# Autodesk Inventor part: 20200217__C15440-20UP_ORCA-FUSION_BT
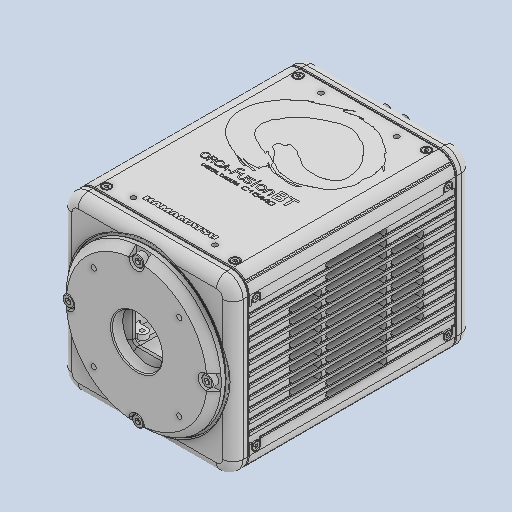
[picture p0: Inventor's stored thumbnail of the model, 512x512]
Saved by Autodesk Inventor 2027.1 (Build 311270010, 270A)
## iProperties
Created: 2020-02
Part Number: 20200217__C15440-20UP_ORCA-FUSION_BT
Material: Generic
Description: STEP AP203
Document SubType Name: Modeling
Designer: dunge
Density: 1 g/cm^3
Appearance: Default
Title: 20200217__C15440-20UP_ORCA-FUSION_BT.STEP
Revision Number: ANY
Sending System: SolidWorks 2018
Preprocessor: SwSTEP 2.0
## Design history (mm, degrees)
feature "B1084-01__B1064-10E01A__FRONT-PANEL-2-solid1"
feature "B1084-01G02__HS-BASE-4_B1084-01__B1064-10__kqb2l06_m5-1-soli"
feature "B1084-01G02__HS-BASE-4_B1084-01__B1064-10__kqb2l06_m5-2-soli"
feature "B1084-01_B1064-10C02__REAR-PANEL_SILK-1_B1064-10C02__REAR-PA"
feature "B1084-01_B1064-10C02__REAR-PANEL_SILK-1_B1064-10C02__REAR-PA"
feature "B1084-01_B1064-10C02__REAR-PANEL_SILK-1_B1064-10C02__REAR-PA"
feature "B1084-01_B1064-10C02__REAR-PANEL_SILK-1_B1064-10C02__REAR-PA"
feature "B1084-01_B1064-10C02__REAR-PANEL_SILK-1_B1064-10C02__REAR-PA"
feature "B1084-01_B1064-10C02__REAR-PANEL_SILK-1_B1064-10C02__REAR-PA"
feature "B1084-01_B1064-10C02__REAR-PANEL_SILK-1_B1064-10C02__REAR-PA"
feature "B1084-01_B1064-10C02__REAR-PANEL_SILK-1_B1064-10C02__REAR-PA"
feature "B1084-01_B1064-10C02__REAR-PANEL_SILK-1_B1064-10C02__REAR-PA"
feature "B1084-01_B1064-10C02__REAR-PANEL_SILK-1_B1064-10C02__REAR-PA"
feature "B1084-01_B1064-10C02__REAR-PANEL_SILK-1_B1064-10C02__REAR-PA"
feature "B1084-01_B1064-10C02__REAR-PANEL_SILK-1_B1064-10C02__REAR-PA"
feature "B1084-01_B1064-10C02__REAR-PANEL_SILK-1_B1064-10C02__REAR-PA"
feature "B1084-01_B1064-10C02__REAR-PANEL_SILK-1_B1064-10C02__REAR-PA"
feature "B1084-01_B1064-10C02__REAR-PANEL_SILK-1_B1064-10C02__REAR-PA"
feature "B1084-01_B1064-10C02__REAR-PANEL_SILK-1_B1064-10C02__REAR-PA"
feature "B1084-01_B1064-10C02__REAR-PANEL_SILK-1_B1064-10C02__REAR-PA"
feature "B1084-01_B1064-10C02__REAR-PANEL_SILK-1_B1064-10C02__REAR-PA"
feature "B1084-01_B1064-10C02__REAR-PANEL_SILK-1_B1064-10C02__REAR-PA"
feature "B1084-01_B1064-10C02__REAR-PANEL_SILK-1_B1064-10C02__REAR-PA"
feature "B1084-01_B1064-10C02__REAR-PANEL_SILK-1_B1064-10C02__REAR-PA"
feature "B1084-01_B1064-10C02__REAR-PANEL_SILK-1_B1064-10C02__REAR-PA"
feature "B1084-01_B1064-10C02__REAR-PANEL_SILK-1_B1064-10C02__REAR-PA"
feature "B1084-01_B1064-10C02__REAR-PANEL_SILK-1_B1064-10C02__REAR-PA"
feature "B1084-01_B1064-10C02__REAR-PANEL_SILK-1_B1064-10C02__REAR-PA"
feature "B1084-01_B1064-10C02__REAR-PANEL_SILK-1_B1064-10C02__REAR-PA"
feature "B1084-01_B1064-10C02__REAR-PANEL_SILK-1_B1064-10C02__REAR-PA"
feature "B1084-01_B1064-10C02__REAR-PANEL_SILK-1_B1064-10C02__REAR-PA"
feature "B1084-01_B1064-10C02__REAR-PANEL_SILK-1_B1064-10C02__REAR-PA"
feature "B1084-01_B1064-10C02__REAR-PANEL_SILK-1_B1064-10C02__REAR-PA"
feature "B1084-01_B1064-10C02__REAR-PANEL_SILK-1_B1064-10C02__REAR-PA"
feature "B1084-01_B1064-10C02__REAR-PANEL_SILK-1_B1064-10C02__REAR-PA"
feature "B1084-01_B1064-10C02__REAR-PANEL_SILK-1_B1064-10C02__REAR-PA"
feature "B1084-01_B1064-10C02__REAR-PANEL_SILK-1_B1064-10C02__REAR-PA"
feature "B1084-01_B1064-10C02__REAR-PANEL_SILK-1_B1064-10C02__REAR-PA"
feature "B1084-01_B1064-10C02__REAR-PANEL_SILK-1_B1064-10C02__REAR-PA"
feature "B1084-01_B1064-10C02__REAR-PANEL_SILK-1_B1064-10C02__REAR-PA"
feature "B1084-01_B1064-10C02__REAR-PANEL_SILK-1_B1064-10C02__REAR-PA"
feature "B1084-01_B1064-10C02__REAR-PANEL_SILK-1_B1064-10C02__REAR-PA"
feature "B1084-01_B1064-10C02__REAR-PANEL_SILK-1_B1064-10C02__REAR-PA"
feature "B1084-01_B1064-10C02__REAR-PANEL_SILK-1_B1064-10C02__REAR-PA"
feature "B1084-01_B1064-10C02__REAR-PANEL_SILK-1_B1064-10C02__REAR-PA"
feature "B1084-01_B1064-10C02__REAR-PANEL_SILK-1_B1064-10C02__REAR-PA"
feature "B1084-01_B1064-10C02__REAR-PANEL_SILK-1_B1064-10C02__REAR-PA"
feature "B1084-01_B1064-10C02__REAR-PANEL_SILK-1_B1064-10C02__REAR-PA"
feature "B1084-01_B1064-10C02__REAR-PANEL_SILK-1_B1064-10C02__REAR-PA"
feature "B1084-01_B1064-10C02__REAR-PANEL_SILK-1_B1064-10C02__REAR-PA"
feature "B1084-01_B1064-10C02__REAR-PANEL_SILK-1_B1064-10C02__REAR-PA"
feature "B1084-01_B1064-10C02__REAR-PANEL_SILK-1_B1064-10C02__REAR-PA"
feature "B1084-01_B1064-10C02__REAR-PANEL_SILK-1_B1064-10C02__REAR-PA"
feature "B1084-01_B1064-10C02__REAR-PANEL_SILK-1_B1064-10C02__REAR-PA"
feature "B1084-01_B1064-10C02__REAR-PANEL_SILK-1_B1064-10C02__REAR-PA"
feature "B1084-01_B1064-10C02__REAR-PANEL_SILK-1_B1064-10C02__REAR-PA"
feature "B1084-01_B1064-10C02__REAR-PANEL_SILK-1_B1064-10C02__REAR-PA"
feature "B1084-01_B1064-10C02__REAR-PANEL_SILK-1_B1064-10C02__REAR-PA"
feature "B1084-01_B1064-10C02__REAR-PANEL_SILK-1_B1064-10C02__REAR-PA"
feature "B1084-01_B1064-10C02__REAR-PANEL_SILK-1_B1064-10C02__REAR-PA"
feature "B1084-01_B1064-10C02__REAR-PANEL_SILK-1_B1064-10C02__REAR-PA"
feature "B1084-01_B1064-10C02__REAR-PANEL_SILK-1_B1064-10C02__REAR-PA"
feature "B1084-01_B1064-10C02__REAR-PANEL_SILK-1_B1064-10C02__REAR-PA"
feature "B1084-01_B1064-10C02__REAR-PANEL_SILK-1_B1064-10C02__REAR-PA"
feature "B1084-01__B1064-10E03A__SIDE-COVER-R-1-solid1"
feature "B1084-01__B1064-10E04A__SIDE-COVER-L-1-solid1"
feature "B1084-01E05__TOP-COVER-1-solid1"
feature "B1084-01E05__TOP-COVER-1-solid2"
feature "B1084-01E06__BOTTOM-COVER-1-solid1"
feature "B1084-01__B1064-10A01__FB-SPACER-02-1-solid1"
feature "B1084-01__B1064-10A01__FB-SPACER-02-4-solid1"
feature "B1084-01__B1064-10A02__FB-SPACER-01-4-solid1"
feature "B1084-01__B1064-10B08__C-MOUNT-1-solid1"
feature "B1084-01__B1064-10A03__CONNE-COVER-1-solid1"
feature "B1084-01__¸§qlW__0Ôix2í__M2x4__3BC-1-solid1"
feature "B1084-01__¸§qlW__0Ôix2í__M2x4__3BC-2-solid1"
feature "B1084-01__Zpt«{g__M2x4__BK-1-solid1"
feature "B1084-01__Zpt«{g__M2x4__BK-2-solid1"
feature "B1084-01__Zpt«{g__M2x4__BK-3-solid1"
feature "B1084-01__Zpt«{g__M2x4__BK-4-solid1"
feature "B1084-01__Zpt«{g__M2x4__BK-5-solid1"
feature "B1084-01__Zpt«{g__M2x4__BK-6-solid1"
feature "B1084-01__Zpt«{g__M2x4__BK-7-solid1"
feature "B1084-01__Zpt«{g__M2x4__BK-8-solid1"
feature "B1084-01__Zpt«{g__M2x4__BK-9-solid1"
feature "B1084-01__Zpt«{g__M2x4__BK-10-solid1"
feature "B1084-01__Zpt«{g__M2x4__BK-11-solid1"
feature "B1084-01__Zpt«{g__M2x4__BK-12-solid1"
feature "B1084-01__Zpt«{g__M2x4__BK-13-solid1"
feature "B1084-01__Zpt«{g__M2x4__BK-14-solid1"
feature "B1084-01__Zpt«{g__M2x4__BK-15-solid1"
feature "B1084-01__Zpt«{g__M2x4__BK-16-solid1"
feature "B1084-01__Zpt«{g__M3x6__X-5-solid1"
feature "B1084-01__Zpt«{g__M3x6__X-6-solid1"
feature "B1084-01__Zpt«{g__M3x6__X-7-solid1"
feature "B1084-01__Zpt«{g__M3x6__X-8-solid1"
feature "B1084-01__B1064__Gen4_LOGO-SILK-HC-3-1-solid1"
feature "B1084-01__B1064__Gen4_LOGO-SILK-HC-3-1-solid2"
feature "B1084-01__B1064__Gen4_LOGO-SILK-HC-3-1-solid3"
feature "B1084-01__B1064__Gen4_LOGO-SILK-HC-3-1-solid4"
feature "B1084-01__B1064__Gen4_LOGO-SILK-HC-3-1-solid5"
feature "B1084-01__B1064__Gen4_LOGO-SILK-HC-3-1-solid6"
feature "B1084-01__B1064__Gen4_LOGO-SILK-HC-3-1-solid7"
feature "B1084-01__B1064__Gen4_LOGO-SILK-HC-3-1-solid8"
feature "B1084-01__B1064__Gen4_LOGO-SILK-HC-3-1-solid9"
feature "B1084-01__B1064__Gen4_LOGO-SILK-HC-3-1-solid10"
feature "B1084-01__B1064__Gen4_LOGO-SILK-HC-3-1-solid11"
feature "B1084-01__B1064__Gen4_LOGO-SILK-HC-3-1-solid12"
feature "B1084-01__B1064__Gen4_LOGO-SILK-HC-3-1-solid13"
feature "B1084-01__B1064__Gen4_LOGO-SILK-HC-3-1-solid14"
feature "B1084-01__B1064__Gen4_LOGO-SILK-HC-3-1-solid15"
feature "B1084-01__B1064__Gen4_LOGO-SILK-HC-3-1-solid16"
feature "B1084-01__B1064__Gen4_LOGO-SILK-HC-3-1-solid17"
feature "B1084-01__B1064__Gen4_LOGO-SILK-HC-3-1-solid18"
feature "B1084-01__B1064__Gen4_LOGO-SILK-HC-3-1-solid19"
feature "B1084-01__B1064__Gen4_LOGO-SILK-HC-3-1-solid20"
feature "B1084-01__B1064__Gen4_LOGO-SILK-HC-3-1-solid21"
feature "B1084-01__B1064__Gen4_LOGO-SILK-HC-3-1-solid22"
feature "B1084-01__B1064__Gen4_LOGO-SILK-HC-3-1-solid23"
feature "B1084-01__B1064__Gen4_LOGO-SILK-HC-3-1-solid24"
feature "B1084-01__B1064__Gen4_LOGO-SILK-HC-3-1-solid25"
feature "B1084-01__B1064__Gen4_LOGO-SILK-HC-3-1-solid26"
feature "B1084-01__B1064__Gen4_LOGO-SILK-HC-3-1-solid27"
feature "B1084-01__B1064__Gen4_LOGO-SILK-HC-3-1-solid28"
feature "B1084-01__B1064__Gen4_LOGO-SILK-HC-3-1-solid29"
feature "B1084-01__B1064__Gen4_LOGO-SILK-HC-3-1-solid30"
feature "B1084-01__B1064__Gen4_LOGO-SILK-HC-3-1-solid31"
feature "B1084-01__B1064__Gen4_LOGO-SILK-HC-3-1-solid32"
feature "B1084-01__B1064__Gen4_LOGO-SILK-HC-3-1-solid33"
feature "B1084-01__B1064__Gen4_LOGO-SILK-HC-3-1-solid34"
feature "B1084-01__B1064__Gen4_LOGO-SILK-HC-3-1-solid35"
feature "B1084-01__B1064__Gen4_LOGO-SILK-HC-3-1-solid36"
feature "B1084-01__B1064__Gen4_LOGO-SILK-HC-3-1-solid37"
feature "B1084-01__B1064__Gen4_LOGO-SILK-HC-3-1-solid38"
feature "B1084-01__B1064__Gen4_LOGO-SILK-HC-3-1-solid39"
feature "B1084-01__B1064__Gen4_LOGO-SILK-HC-3-1-solid40"
feature "B1084-01__B1064__Gen4_LOGO-SILK-HC-3-1-solid41"
feature "B1084-01__B1064__Gen4_LOGO-SILK-HC-3-1-solid42"
feature "B1084-01__B1064__Gen4_LOGO-SILK-HC-3-1-solid43"
body "Solid1"
body "Solid2"
body "Solid3"
body "Solid4"
body "Solid5"
body "Solid6"
body "Solid7"
body "Solid8"
body "Solid9"
body "Solid10"
body "Solid11"
body "Solid12"
body "Solid13"
body "Solid14"
body "Solid15"
body "Solid16"
body "Solid17"
body "Solid18"
body "Solid19"
body "Solid20"
body "Solid21"
body "Solid22"
body "Solid23"
body "Solid24"
body "Solid25"
body "Solid26"
body "Solid27"
body "Solid28"
body "Solid29"
body "Solid30"
body "Solid31"
body "Solid32"
body "Solid33"
body "Solid34"
body "Solid35"
body "Solid36"
body "Solid37"
body "Solid38"
body "Solid39"
body "Solid40"
body "Solid41"
body "Solid42"
body "Solid43"
body "Solid44"
body "Solid45"
body "Solid46"
body "Solid47"
body "Solid48"
body "Solid49"
body "Solid50"
body "Solid51"
body "Solid52"
body "Solid53"
body "Solid54"
body "Solid55"
body "Solid56"
body "Solid57"
body "Solid58"
body "Solid59"
body "Solid60"
body "Solid61"
body "Solid62"
body "Solid63"
body "Solid64"
body "Solid65"
body "Solid66"
body "Solid67"
body "Solid68"
body "Solid69"
body "Solid70"
body "Solid71"
body "Solid72"
body "Solid73"
body "Solid74"
body "Solid75"
body "Solid76"
body "Solid77"
body "Solid78"
body "Solid79"
body "Solid80"
body "Solid81"
body "Solid82"
body "Solid83"
body "Solid84"
body "Solid85"
body "Solid86"
body "Solid87"
body "Solid88"
body "Solid89"
body "Solid90"
body "Solid91"
body "Solid92"
body "Solid93"
body "Solid94"
body "Solid95"
body "Solid96"
body "Solid97"
body "Solid98"
body "Solid99"
body "Solid100"
body "Solid101"
body "Solid102"
body "Solid103"
body "Solid104"
body "Solid105"
body "Solid106"
body "Solid107"
body "Solid108"
body "Solid109"
body "Solid110"
body "Solid111"
body "Solid112"
body "Solid113"
body "Solid114"
body "Solid115"
body "Solid116"
body "Solid117"
body "Solid118"
body "Solid119"
body "Solid120"
body "Solid121"
body "Solid122"
body "Solid123"
body "Solid124"
body "Solid125"
body "Solid126"
body "Solid127"
body "Solid128"
body "Solid129"
body "Solid130"
body "Solid131"
body "Solid132"
body "Solid133"
body "Solid134"
body "Solid135"
body "Solid136"
body "Solid137"
body "Solid138"
body "Solid139"
body "Solid140"
body "Solid141"
body "Solid142"
body "Solid143"
body "Solid144"
body "Solid145"
body "Solid146"
body "Solid147"
body "Solid148"
body "Solid149"
body "Solid150"
body "Solid151"
body "Solid152"
body "Solid153"
body "Solid154"
body "Solid155"
body "Solid156"
body "Solid157"
body "Solid158"
